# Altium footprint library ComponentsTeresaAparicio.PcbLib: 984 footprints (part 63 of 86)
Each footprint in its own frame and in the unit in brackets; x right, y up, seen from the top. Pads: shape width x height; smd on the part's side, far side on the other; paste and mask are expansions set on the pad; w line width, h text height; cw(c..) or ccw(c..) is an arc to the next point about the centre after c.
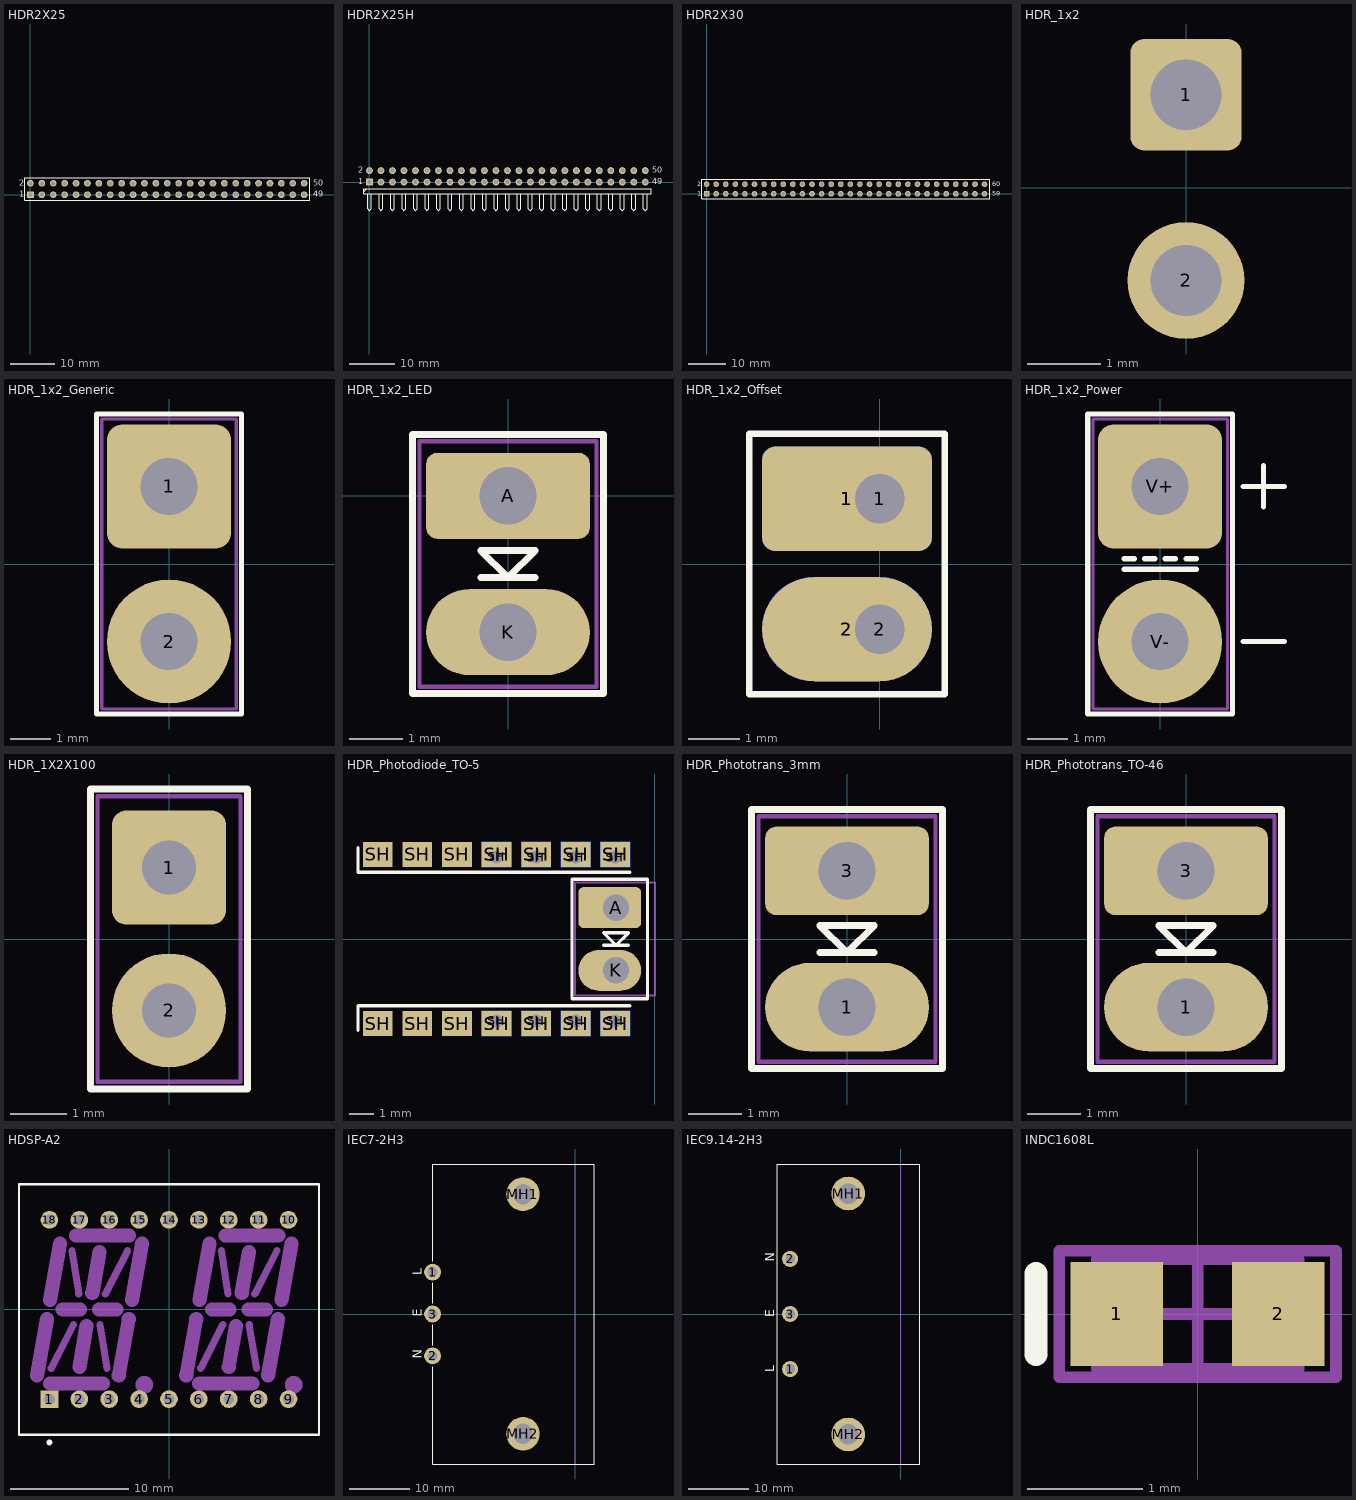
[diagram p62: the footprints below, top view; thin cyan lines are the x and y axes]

## HDR2X25 [mm] "Connector; Header; 25x2 Position"
pads (50):
  rect 1.5x1.5 hole 0.9: 1(0,0)
  round 1.5 hole 0.9: 2(0,2.54) 3(2.54,0) 4(2.54,2.54) 5(5.08,0) 6(5.08,2.54) 7(7.62,0) 8(7.62,2.54) 9(10.16,0) 10(10.16,2.54) 11(12.7,0) 12(12.7,2.54) 13(15.24,0) 14(15.24,2.54) 15(17.78,0) 16(17.78,2.54) 17(20.32,0) 18(20.32,2.54) 19(22.86,0) 20(22.86,2.54) 21(25.4,0) 22(25.4,2.54) 23(27.94,0) 24(27.94,2.54) 25(30.48,0) 26(30.48,2.54) 27(33.02,0) 28(33.02,2.54) 29(35.56,0) 30(35.56,2.54) 31(38.1,0) 32(38.1,2.54) 33(40.64,0) 34(40.64,2.54) 35(43.18,0) 36(43.18,2.54) 37(45.72,0) 38(45.72,2.54) 39(48.26,0) 40(48.26,2.54) 41(50.8,0) 42(50.8,2.54) 43(53.34,0) 44(53.34,2.54) 45(55.88,0) 46(55.88,2.54) 47(58.42,0) 48(58.42,2.54) 49(60.96,0) 50(60.96,2.54)
Top Overlay:
  lines w0.2: -1.27,-1.27 62.23,-1.27 62.23,3.81 -1.27,3.81 -1.27,-1.27
  text "50" at 62.992,2.032 h1.27
  text "49" at 62.992,-0.508 h1.27
  text "1" at -2.54,-0.508 h1.27
  text "2" at -2.54,2.032 h1.27

## HDR2X25H [mm] "Connector; Header; 25x2 Position; Right Angle"
pads (50):
  rect 1.5x1.5 hole 0.9: 1(0,0)
  round 1.5 hole 0.9: 2(0,2.54) 3(2.54,0) 4(2.54,2.54) 5(5.08,0) 6(5.08,2.54) 7(7.62,0) 8(7.62,2.54) 9(10.16,0) 10(10.16,2.54) 11(12.7,0) 12(12.7,2.54) 13(15.24,0) 14(15.24,2.54) 15(17.78,0) 16(17.78,2.54) 17(20.32,0) 18(20.32,2.54) 19(22.86,0) 20(22.86,2.54) 21(25.4,0) 22(25.4,2.54) 23(27.94,0) 24(27.94,2.54) 25(30.48,0) 26(30.48,2.54) 27(33.02,0) 28(33.02,2.54) 29(35.56,0) 30(35.56,2.54) 31(38.1,0) 32(38.1,2.54) 33(40.64,0) 34(40.64,2.54) 35(43.18,0) 36(43.18,2.54) 37(45.72,0) 38(45.72,2.54) 39(48.26,0) 40(48.26,2.54) 41(50.8,0) 42(50.8,2.54) 43(53.34,0) 44(53.34,2.54) 45(55.88,0) 46(55.88,2.54) 47(58.42,0) 48(58.42,2.54) 49(60.96,0) 50(60.96,2.54)
Top Overlay:
  lines w0.2: -1.27,-2.117 -0.635,-1.482 ; -0.423,-2.54 -0.423,-5.927 0,-6.35 0.423,-5.927 0.423,-2.54 ; 2.117,-2.54 2.117,-5.927 2.54,-6.35 2.963,-5.927 2.963,-2.54 ; 4.657,-2.54 4.657,-5.927 5.08,-6.35 5.503,-5.927 5.503,-2.54 ; 7.197,-2.54 7.197,-5.927 7.62,-6.35 8.043,-5.927 8.043,-2.54 ; 9.737,-2.54 9.737,-5.927 10.16,-6.35 10.583,-5.927 10.583,-2.54 ; 12.277,-2.54 12.277,-5.927 12.7,-6.35 13.123,-5.927 13.123,-2.54 ; 14.817,-2.54 14.817,-5.927 15.24,-6.35 15.663,-5.927 15.663,-2.54 ; 17.357,-2.54 17.357,-5.927 17.78,-6.35 18.203,-5.927 18.203,-2.54 ; 19.897,-2.54 19.897,-5.927 20.32,-6.35 20.743,-5.927 20.743,-2.54 ; 22.437,-2.54 22.437,-5.927 22.86,-6.35 23.283,-5.927 23.283,-2.54 ; 24.977,-2.54 24.977,-5.927 25.4,-6.35 25.823,-5.927 25.823,-2.54 ; 27.517,-2.54 27.517,-5.927 27.94,-6.35 28.363,-5.927 28.363,-2.54 ; 30.057,-2.54 30.057,-5.927 30.48,-6.35 30.903,-5.927 30.903,-2.54 ; 32.597,-2.54 32.597,-5.927 33.02,-6.35 33.443,-5.927 33.443,-2.54 ; 35.137,-2.54 35.137,-5.927 35.56,-6.35 35.983,-5.927 35.983,-2.54 ; 37.677,-2.54 37.677,-5.927 38.1,-6.35 38.523,-5.927 38.523,-2.54 ; 40.217,-2.54 40.217,-5.927 40.64,-6.35 41.063,-5.927 41.063,-2.54 ; 42.757,-2.54 42.757,-5.927 43.18,-6.35 43.603,-5.927 43.603,-2.54 ; 45.297,-2.54 45.297,-5.927 45.72,-6.35 46.143,-5.927 46.143,-2.54 ; 47.837,-2.54 47.837,-5.927 48.26,-6.35 48.683,-5.927 48.683,-2.54 ; 50.377,-2.54 50.377,-5.927 50.8,-6.35 51.223,-5.927 51.223,-2.54 ; 52.917,-2.54 52.917,-5.927 53.34,-6.35 53.763,-5.927 53.763,-2.54 ; 55.457,-2.54 55.457,-5.927 55.88,-6.35 56.303,-5.927 56.303,-2.54 ; 57.997,-2.54 57.997,-5.927 58.42,-6.35 58.843,-5.927 58.843,-2.54 ; 60.537,-2.54 60.537,-5.927 60.96,-6.35 61.383,-5.927 61.383,-2.54 ; -1.27,-2.54 -1.27,-1.482 62.23,-1.482 62.23,-2.54 -1.27,-2.54
  text "2" at -2.54,2.032 h1.27
  text "1" at -2.54,-0.508 h1.27
  text "49" at 62.484,-0.508 h1.27
  text "50" at 62.484,2.032 h1.27

## HDR2X30 [mm] "Connector; Header; 30x2 Position"
pads (60):
  rect 1.5x1.5 hole 0.9: 1(0,0)
  round 1.5 hole 0.9: 2(0,2.54) 3(2.54,0) 4(2.54,2.54) 5(5.08,0) 6(5.08,2.54) 7(7.62,0) 8(7.62,2.54) 9(10.16,0) 10(10.16,2.54) 11(12.7,0) 12(12.7,2.54) 13(15.24,0) 14(15.24,2.54) 15(17.78,0) 16(17.78,2.54) 17(20.32,0) 18(20.32,2.54) 19(22.86,0) 20(22.86,2.54) 21(25.4,0) 22(25.4,2.54) 23(27.94,0) 24(27.94,2.54) 25(30.48,0) 26(30.48,2.54) 27(33.02,0) 28(33.02,2.54) 29(35.56,0) 30(35.56,2.54) 31(38.1,0) 32(38.1,2.54) 33(40.64,0) 34(40.64,2.54) 35(43.18,0) 36(43.18,2.54) 37(45.72,0) 38(45.72,2.54) 39(48.26,0) 40(48.26,2.54) 41(50.8,0) 42(50.8,2.54) 43(53.34,0) 44(53.34,2.54) 45(55.88,0) 46(55.88,2.54) 47(58.42,0) 48(58.42,2.54) 49(60.96,0) 50(60.96,2.54) 51(63.5,0) 52(63.5,2.54) 53(66.04,0) 54(66.04,2.54) 55(68.58,0) 56(68.58,2.54) 57(71.12,0) 58(71.12,2.54) 59(73.66,0) 60(73.66,2.54)
Top Overlay:
  lines w0.2: -1.27,-1.27 75.06,-1.27 75.06,3.81 -1.27,3.81 -1.27,-1.27
  text "60" at 75.692,2.032 h1.27
  text "59" at 75.692,-0.508 h1.27
  text "1" at -2.54,-0.508 h1.27
  text "2" at -2.54,2.032 h1.27
Bottom Overlay:
  text "1" at -55.88,-0.508 h1.27

## HDR_1x2 [mil]
pads (2):
  rrect25% 60x60 hole 38: 1(0,50)
  round 62.99 hole 38: 2(0,-50)

## HDR_1x2_Generic [mil] "Connector Header, Single-row 2-position, 0.200\" pitch"
height 235
pads (2):
  rrect25% 120x120 hole 55: 1(0,75)
  round 120 hole 55: 2(0,-75)
Top Overlay:
  lines w5: -70,-145 70,-145 70,145 -70,145 -70,-145
Mechanical 13:
  lines w3: -65,-140 65,-140 65,140 -65,140 -65,-140

## HDR_1x2_LED [mil] "Connector Header, Single-row 2-position, 0.100\" pitch"
height 235
pads (2):
  rrect25% 120x63 hole 42: A(0,0)
  oval 120x63 hole 42: K(0,-100)
Top Overlay:
  lines w5: -20,-60 20,-60 ; -70,-145 70,-145 70,45 -70,45 -70,-145 ; -20,-40 0,-60 20,-40 -20,-40
Mechanical 13:
  lines w3: -65,-140 65,-140 65,40 -65,40 -65,-140

## HDR_1x2_Offset [mil]
pads (6):
  rrect25% 130x80 smd far side: 1(-25,50)
  rrect25% 130x80 smd: 1(-25,50)
  rrect25% 60x60 hole 38: 1(0,50)
  oval 130x80 smd far side: 2(-25,-50)
  oval 130x80 smd: 2(-25,-50)
  round 60 hole 38: 2(0,-50)
Top Overlay:
  lines w5: -100,-100 -100,100 50,100 50,-100 -100,-100

## HDR_1x2_Power [mil] "Connector Header, Single-row 2-position, 0.200\" pitch"
height 235
pads (2):
  rrect25% 120x120 hole 55: V+(0,75)
  round 120 hole 55: V-(0,-75)
Top Overlay:
  lines w5: -35,-5 35,-5 ; -35,5 -25,5 ; -15,5 -5,5 ; 5,5 15,5 ; 25,5 35,5 ; 80,-75 120,-75 ; 80,75 120,75 ; 100,55 100,95 ; -70,-145 70,-145 70,145 -70,145 -70,-145
Mechanical 13:
  lines w3: -65,-140 65,-140 65,140 -65,140 -65,-140

## HDR_1X2X100 [mil]
pads (2):
  rrect25% 80x80 hole 38: 1(0,50)
  round 80 hole 38: 2(0,-50)
Top Overlay:
  lines w5: -55,-105 55,-105 55,105 -55,105 -55,-105
Mechanical 13:
  lines w3: -50,-100 50,-100 50,100 -50,100 -50,-100

## HDR_Photodiode_TO-5 [mil] "Photodiode TO-5 form, edge straddling"
height 525
pads (33):
  round 10 on Mech14: 0(0,0)
  rrect25% 100x65 hole 42 copper offset -10,0: A(-61.81,50)
  oval 100x65 hole 42 copper offset -10,0: K(-61.81,-50)
  rect 47.24x40 smd: SH(-440.94,-134.49) SH(-440.94,134.5) SH(-377.95,-134.5) SH(-377.95,134.49) SH(-314.96,-134.5) SH(-314.96,134.49) SH(-251.97,-134.49) SH(-251.97,134.51) SH(-188.98,-134.49) SH(-188.98,134.5) SH(-125.99,-134.49) SH(-125.99,134.5) SH(-63,-134.49) SH(-63,134.5)
  rect 47.24x40 smd far side: SH(-251.97,-134.49) SH(-251.97,134.51) SH(-188.98,-134.49) SH(-188.98,134.5) SH(-125.99,-134.49) SH(-125.99,134.5) SH(-63,-134.49) SH(-63,134.5)
  round 32 hole 20: SH(-251.97,-130.49) SH(-251.97,130.51) SH(-188.98,-130.49) SH(-188.98,130.5) SH(-125.99,-130.49) SH(-125.99,130.5) SH(-63,-130.49) SH(-63,130.5)
Top Overlay:
  lines w5: -472.44,-145.66 -472.44,-106.29 -39.37,-106.29 ; -472.44,145.67 -472.44,106.3 -39.37,106.3 ; -81.81,-10 -41.81,-10 ; -131.81,-95 -131.81,95 -11.81,95 -11.81,-95 -131.81,-95 ; -81.81,10 -41.81,10 -61.81,-10 -81.81,10
Mechanical 13:
  lines w3: -126.81,-90 -126.81,90 0,90 0,-90 -126.81,-90
3D body: height 109.1, standoff -172.1, extent -444.88,-140.32 86.62,140.32

## HDR_Phototrans_3mm [mil] "LED 3mm dia lens, 0.100\" pitch"
height 525
pads (2):
  oval 120x65 hole 42: 1(0,-50)
  rrect25% 120x65 hole 42: 3(0,50)
Top Overlay:
  lines w5: -20,-10 20,-10 ; -70,-95 70,-95 70,95 -70,95 -70,-95 ; -20,10 0,-10 20,10 -20,10
Mechanical 13:
  lines w3: -65,-90 65,-90 65,90 -65,90 -65,-90
3D body: height 31, standoff -94.49, extent -249.2,-62.86 516.54,62.87

## HDR_Phototrans_TO-46 [mil] "LED TO-46 form, edge straddling"
height 525
pads (2):
  oval 120x65 hole 42: 1(0,-50)
  rrect25% 120x65 hole 42: 3(0,50)
Top Overlay:
  lines w5: -20,-10 20,-10 ; -70,-95 -70,95 70,95 70,-95 -70,-95 ; -20,10 20,10 0,-10 -20,10
Mechanical 13:
  lines w3: -65,-90 -65,90 65,90 65,-90 -65,-90
3D body: height 77.29, standoff -150.51, extent -8.99,-119.01 546.86,108.79

## HDSP-A2 [mm] "LED, Alphanumeric Display, 13.8 mm, Dual Character; 18 Leads; Row Space 15.24 mm; Pitch 2.54 mm"
height 7.27
pads (18):
  rect 1.5x1.5 hole 0.9: 1(-10.16,-7.62)
  round 1.5 hole 0.9: 2(-7.62,-7.62) 3(-5.08,-7.62) 4(-2.54,-7.62) 5(0,-7.62) 6(2.54,-7.62) 7(5.08,-7.62) 8(7.62,-7.62) 9(10.16,-7.62) 10(10.16,7.62) 11(7.62,7.62) 12(5.08,7.62) 13(2.54,7.62) 14(0,7.62) 15(-2.54,7.62) 16(-5.08,7.62) 17(-7.62,7.62) 18(-10.16,7.62)
Top Overlay:
  circle w0.25: c-10.16,-11.3 r0.125
  lines w0.2: -12.75,-10.65 12.75,-10.65 12.75,10.65 -12.75,10.65 -12.75,-10.65
Mechanical 1:
  circle w1.2: c-2.1,-6.4 r0.15
  circle w1.2: c10.6,-6.4 r0.15
  lines w0.6: -10.01,-5 -8.12,-1.3 ; -8.25,5 -7.67,1.3 ; -5.88,-1.3 -5.28,-5 ; -5.42,1.3 -3.52,5 ; 2.69,-5 4.58,-1.3 ; 4.45,5 5.03,1.3 ; 6.82,-1.3 7.42,-5 ; 7.28,1.3 9.18,5
  lines w1.2: -11.23,-5.6 -10.38,-0.8 ; -10.13,-6.3 -5.62,-6.3 ; -10.1,0.8 -9.26,5.58 ; -9.035,0 -7.58,0 ; -7.9,6.3 -3.39,6.3 ; -7.62,-4.89 -7.01,-1.4 ; -6.52,1.41 -5.91,4.89 ; -5.96,0 -4.465,0 ; -4.27,-5.6 -3.42,-0.8 ; -3.13,0.81 -2.3,5.59 ; 1.47,-5.6 2.32,-0.8 ; 2.57,-6.3 7.08,-6.3 ; 2.6,0.8 3.44,5.58 ; 3.665,0 5.14,0 ; 4.8,6.3 9.31,6.3 ; 5.08,-4.89 5.69,-1.4 ; 6.18,1.41 6.79,4.89 ; 6.76,0 8.235,0 ; 8.43,-5.6 9.28,-0.8 ; 9.57,0.81 10.4,5.59
Mechanical 13:
  lines w0.1: -12.75,-10.65 -12.75,10.65 12.75,10.65 12.75,-10.65 -12.75,-10.65
3D body: height 7.27, standoff 0, extent -12.75,-10.65 12.75,10.65

## IEC7-2H3 [mm] "Mains Power Outlet, IEC60 320-2-2 F, PC Flange Rear Mount"
height 30.4
pads (5):
  round 2.8 hole 1.7: 1(-23.8,7) 2(-23.8,-7) 3(-23.8,0)
  round 5.6 hole 3.4: MH1(-8.7,20) MH2(-8.7,-20)
Top Overlay:
  lines w0.2: -23.8,-8.8 -23.8,-25.05 3.2,-25.05 3.2,25.05 -23.8,25.05 -23.8,8.8 ; -23.8,-5.2 -23.8,-1.8 ; -23.8,1.8 -23.8,5.2
  text "L" at -25.6,6.5 h1.5
  text "E" at -25.6,-0.5 h1.5
  text "N" at -25.6,-7.5 h1.5
Mechanical 1:
  lines w0.1: 0,-25.05 0,25.05
  text "PCB Edge" at -0.4,-24.4 h0.5

## IEC9.14-2H3 [mm] "Mains Power Inlet, IEC60 320-1 C14, PC Flange Rear Mount"
height 27.8
pads (5):
  round 2.65 hole 1.6: 1(-18.35,-9.14) 2(-18.35,9.14) 3(-18.35,0)
  round 5.6 hole 3.4: MH1(-8.7,20) MH2(-8.7,-20)
Top Overlay:
  lines w0.2: -20.5,-24.9 -20.5,24.9 3.2,24.9 3.2,-24.9 -20.5,-24.9
  text "N" at -21,8.64 h1.5
  text "E" at -21,-0.5 h1.5
  text "L" at -21,-9.64 h1.5
Mechanical 1:
  lines w0.1: 0,-24.9 0,24.9
  text "PCB Edge" at -0.383,-24.4 h0.5

## INDC1608L [mm] "Chip Inductor, Body 1.6x0.8mm, IPC High Density"
height 0.55
pads (2):
  rect 0.8x0.9 smd: 1(-0.7,0) 2(0.7,0)
Top Overlay:
  lines w0.2: -1.4,-0.35 -1.4,0.35
Mechanical 13:
  lines w0.1: -0.875,-0.475 -0.875,0.475 0.875,0.475 0.875,-0.475 -0.875,-0.475
Mechanical 15:
  lines w0.1: -0.475,0 0.475,0 ; 0,-0.475 0,0.475 ; -1.2,-0.55 -1.2,0.55 1.2,0.55 1.2,-0.55 -1.2,-0.55
3D body: height 0.55, standoff 0, extent -0.875,-0.475 0.875,0.475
